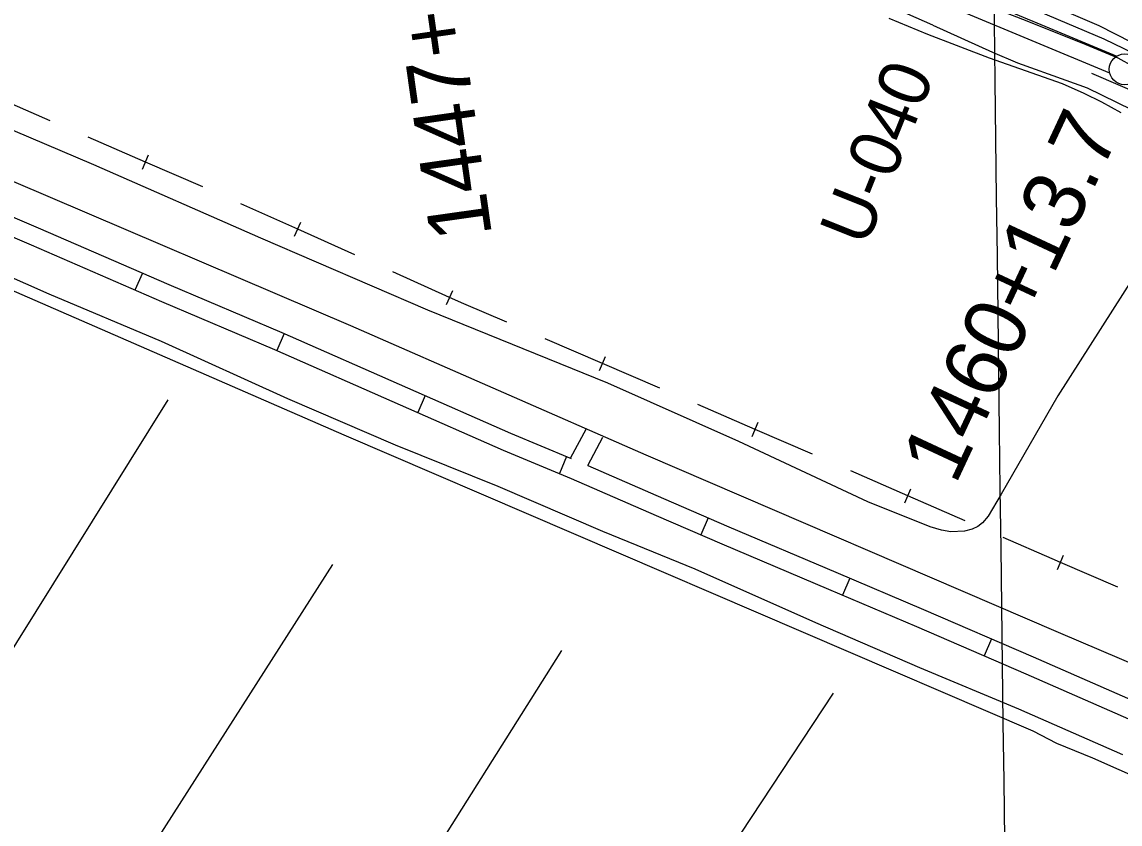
# Model space of a CAD drawing. Extents: x 3734862 to 3772949, y 391520 to 417239.
# Drawn here: x 3740026 to 3741807, y 404013 to 405314 of the extents above; entities that cross this region are included whole.
import ezdxf

# ---------------------------------------------------------------- set-up
doc = ezdxf.new("R2010")
doc.units = 0
for name, color, linetype in [('V-DTCH-CNTR', 7, 'Continuous'), ('V-FLOD-BASE', 7, 'Continuous'), ('V-GRID-MAJR', 7, 'Continuous'), ('V-LEVE-TOET', 7, 'Continuous'), ('V-RAIL-TRAK', 7, 'Continuous'), ('V-RIVR-EDGE', 7, 'Continuous'), ('V-RIVR-RANG-IDEN', 7, 'Continuous'), ('V-ROAD-CNTR', 7, 'Continuous'), ('V-RRAP-FSHR', 7, 'Continuous'), ('V-SITE-VEGE', 7, 'Continuous'), ('V-SURV-IDEN', 7, 'Continuous'), ('V-SURV-LINE', 7, 'Continuous'), ('V-TOPO-MINR', 7, 'Continuous'), ('V-TOPO-SHOR', 7, 'Continuous')]:
    doc.layers.add(name, color=color, linetype=linetype)

msp = doc.modelspace()

# ---------------------------------------------------------------- linework, layer by layer
at = {"layer": 'V-DTCH-CNTR'}
msp.add_lwpolyline([(3741974.8559930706, 404024.44664253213), (3741944.0631581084, 404044.97519917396), (3741899.5846187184, 404062.08232970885), (3741848.263227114, 404082.6108863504), (3741762.7275744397, 404120.2465735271), (3741704.5633306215, 404144.1965562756), (3741665.9262504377, 404164.015792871), (3740548.1213064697, 404644.43408793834), (3739663.390584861, 405029.7200473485), (3738935.6282170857, 405348.413371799)], dxfattribs=at)
at = {"layer": 'V-FLOD-BASE'}
msp.add_lwpolyline([(3741566.42, 405351.376), (3741658.144, 405314.952), (3741751.273, 405278.068), (3741803.036, 405256.38300000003), (3741828.798, 405242.037)], dxfattribs=at)
at = {"layer": 'V-GRID-MAJR'}
msp.add_spline([(3741709.628, 396887.316), (3741632.95, 402946.574), (3741556.258, 409006.89400000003), (3741479.5670000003, 415067.217), (3741479.554, 415068.275)], degree=3, dxfattribs=at)
at = {"layer": 'V-LEVE-TOET'}
for points in [[(3741503.139, 405309.107), (3741231.974, 405429.489), (3740957.71, 405546.288), (3740650.096, 405671.458), (3740361.478, 405794.487), (3740102.598, 405906.083), (3739811.915, 406027.064), (3739535.06, 406138.742)], [(3741628.659, 405352.199), (3741780.312, 405287.128), (3741845.3910000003, 405255.703), (3741955.395, 405188.083), (3742116.45, 405092.701), (3742264.876, 405000.525), (3742443.403, 404886.08400000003), (3742584.272, 404792.468), (3742604.416, 404780.428), (3742616.125, 404773.95), (3742646.525, 404765.232), (3742696.1010000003, 404751.478), (3742794.686, 404725.364), (3742931.427, 404690.103), (3743095.855, 404647.04600000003), (3743222.298, 404615.939), (3743373.072, 404576.548), (3743548.44, 404530.746), (3743737.366, 404483.145), (3743928.0700000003, 404434.619), (3744115.492, 404387.945)], [(3741503.139, 405309.107), (3741600.038, 405265.704), (3741640.292, 405248.163), (3741718.896, 405220.078), (3741753.522, 405207.645), (3741825.157, 405172.52)]]:
    msp.add_lwpolyline(points, dxfattribs=at)
at = {"layer": 'V-RAIL-TRAK'}
for points in [[(3740071.17, 405154.295), (3739978.271, 405194.56)], [(3740226.003, 405087.189), (3740133.1040000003, 405127.453)], [(3740221.032, 405075.719), (3740230.974, 405098.658)], [(3740318.903, 405046.924), (3740226.003, 405087.189)], [(3740473.021, 404978.197), (3740380.642, 405019.642)], [(3740467.904, 404966.792), (3740478.1380000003, 404989.601)], [(3740565.4, 404936.751), (3740473.021, 404978.197)], [(3740719.364, 404867.675), (3740626.986, 404909.121)], [(3740714.248, 404856.271), (3740724.481, 404879.08)], [(3740812.198, 404827.264), (3740742.468, 404857.31), (3740719.364, 404867.675)], [(3740967.173, 404760.487), (3740874.188, 404800.553)], [(3740962.227, 404749.007), (3740972.12, 404771.967)], [(3741060.159, 404720.42100000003), (3740967.173, 404760.487)], [(3741215.134, 404653.64400000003), (3741122.149, 404693.71)], [(3741210.188, 404642.164), (3741220.08, 404665.123)], [(3741308.119, 404613.577), (3741215.134, 404653.64400000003)], [(3741462.737, 404545.976), (3741369.967, 404586.538)], [(3741457.7290000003, 404534.523), (3741467.745, 404557.429)], [(3741555.507, 404505.414), (3741462.737, 404545.976)], [(3741710.149, 404437.87), (3741696.799, 404443.63800000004), (3741617.3540000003, 404478.373)], [(3741705.1920000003, 404426.395), (3741715.1070000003, 404449.344)], [(3741803.095, 404397.711), (3741710.149, 404437.87)]]:
    msp.add_lwpolyline(points, dxfattribs=at)
at = {"layer": 'V-RIVR-EDGE'}
msp.add_spline([(3740284.2251414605, 406091.4953103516), (3740310.8823887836, 406078.8939307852), (3740348.850922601, 406061.81651383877), (3740353.7003308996, 406060.5914132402), (3740364.615249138, 406059.3513143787), (3740372.6955965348, 406056.5007453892), (3740387.627191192, 406044.3327297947), (3740395.708538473, 406041.8865281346), (3740409.039661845, 406036.59675667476), (3740430.0417658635, 406026.43557946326), (3740442.5591551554, 406019.1259711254), (3740451.446237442, 406015.4646677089), (3740465.996462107, 406012.59810057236), (3740476.5040133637, 406010.1458996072), (3740489.4327691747, 406005.6658626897), (3740507.608301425, 405997.1291539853), (3740522.954262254, 405989.00381179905), (3740544.3577339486, 405977.62853271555), (3740556.473755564, 405971.5330262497), (3740569.8088784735, 405967.860724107), (3740577.487858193, 405966.22425698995), (3740592.041082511, 405964.57079184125), (3740596.8934904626, 405964.55879323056), (3740607.3960422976, 405960.0847556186), (3740616.67949284, 405953.1875136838), (3740635.667759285, 405946.26627452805), (3740666.7660480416, 405930.82332493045), (3740697.870336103, 405917.8065793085), (3740711.608826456, 405913.72890995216), (3740727.769521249, 405908.02777197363), (3740737.4643383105, 405903.96010145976), (3740772.597301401, 405884.8678470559), (3740794.413139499, 405876.72650672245), (3740819.459916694, 405866.9596979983), (3740836.4233468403, 405858.8303562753), (3740859.038920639, 405847.04771020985), (3740882.053862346, 405833.2422276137), (3740901.840864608, 405822.2753153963), (3740929.3028470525, 405808.0544667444), (3740946.262277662, 405798.3076557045), (3740968.879851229, 405787.3337442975), (3740998.357671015, 405770.6816922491), (3741025.4092868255, 405754.03563950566), (3741050.8534321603, 405741.4372595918), (3741073.4700058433, 405730.0589808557), (3741090.8378033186, 405721.9286392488), (3741112.2472743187, 405712.9795641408), (3741151.0305421, 405698.32635140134), (3741164.764033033, 405692.22684539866), (3741182.937565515, 405682.8814020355), (3741205.1587708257, 405675.143429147), (3741229.3978132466, 405665.78298752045), (3741250.811283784, 405658.45138172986), (3741277.4785299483, 405649.8936754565), (3741303.738409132, 405640.1238670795), (3741333.2262277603, 405627.51548832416), (3741357.457271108, 405614.920108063), (3741386.5417222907, 405602.71709652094), (3741400.2862119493, 405601.0656311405), (3741418.8691111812, 405593.74102453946), (3741447.554194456, 405583.56084952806), (3741468.5642975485, 405576.63461095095), (3741486.743829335, 405569.7153715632), (3741500.8786879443, 405562.4017636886), (3741512.5913421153, 405556.71162443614), (3741522.6905265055, 405552.64295403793), (3741537.2377515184, 405548.5632849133), (3741581.273795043, 405532.2796043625), (3741608.739777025, 405519.6762250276), (3741642.2532710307, 405499.7792355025), (3741662.8440085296, 405486.7884868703), (3741678.9967042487, 405477.8524102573), (3741697.168236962, 405467.69823223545), (3741715.3337703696, 405455.11785023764), (3741729.8729963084, 405447.8032424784), (3741754.1050395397, 405435.61222954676), (3741802.56612635, 405410.01710169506), (3741822.7624953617, 405401.0710262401), (3741865.5744381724, 405380.34230471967), (3741892.227685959, 405366.1234558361), (3741915.6569938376, 405356.3606466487), (3741930.6035867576, 405350.25814099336), (3741951.2093225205, 405343.33290230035), (3741972.626792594, 405337.6187658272), (3742009.0038540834, 405331.0588989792), (3742028.395487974, 405323.73229260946), (3742041.723611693, 405317.22941916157), (3742042.524347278, 405313.9924807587), (3742046.965388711, 405311.1509107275), (3742058.684042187, 405307.8869754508), (3742068.7932254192, 405307.86197834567), (3742073.6456333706, 405307.8499797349), (3742079.7181424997, 405310.66555277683), (3742088.618223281, 405312.2610246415), (3742095.0831011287, 405310.2231898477), (3742118.5114091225, 405300.05601333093), (3742134.2687364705, 405294.76024256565), (3742159.723880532, 405286.6099032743), (3742182.3504530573, 405279.2752978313), (3742201.342719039, 405273.9715279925), (3742222.3558217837, 405268.2583914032), (3742239.72861868, 405262.14988644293), (3742263.564293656, 405253.1948120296), (3742278.9102544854, 405245.0694698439), (3742307.9867065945, 405229.6315196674), (3742326.1582393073, 405219.4773416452), (3742346.3526085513, 405209.72253153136), (3742373.8245898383, 405199.54535617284), (3742400.8892041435, 405188.1560787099), (3742413.4055935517, 405180.4421030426), (3742429.9596569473, 405170.2919245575), (3742436.0041693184, 405161.78521237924), (3742439.2221099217, 405154.9029687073), (3742444.4658867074, 405149.6331949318), (3742450.526397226, 405147.5963600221), (3742468.3095607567, 405143.91305915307), (3742478.4117448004, 405141.05749074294), (3742497.4000112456, 405134.1362515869), (3742510.3247675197, 405128.03874535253), (3742527.692564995, 405119.90840374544), (3742545.0583627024, 405110.96932747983), (3742567.6769361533, 405100.3997834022), (3742590.6998769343, 405089.82923944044), (3742639.1599638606, 405063.8297442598), (3742649.265147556, 405062.1872778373), (3742658.9699634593, 405062.1632806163), (3742667.4626772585, 405062.54665037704), (3742676.7581264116, 405060.50181639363), (3742690.8999842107, 405056.018779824), (3742714.3282922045, 405045.85160330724), (3742740.9825398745, 405032.0371217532), (3742759.96380713, 405022.2853112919), (3742790.248361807, 405004.8225248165), (3742814.0870364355, 404997.0805523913), (3742826.612424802, 404993.0058826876), (3742844.39258868, 404988.1094798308), (3742862.983486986, 404984.0198118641), (3742878.743813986, 404979.9371430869), (3742899.75191731, 404972.2021698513), (3742910.66483578, 404970.15333633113), (3742935.3102452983, 404961.6006294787), (3742961.1707565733, 404953.8536576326), (3742978.5425535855, 404947.34078534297), (3742993.8905141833, 404940.0241778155), (3743010.454576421, 404933.91767262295), (3743026.218902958, 404931.4524731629), (3743054.51061763, 404925.72133865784), (3743082.401964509, 404921.60867335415), (3743104.22780145, 404917.5110063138), (3743119.989128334, 404913.8327048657), (3743140.19349642, 404908.1215680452), (3743171.309783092, 404899.9572303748), (3743202.021702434, 404891.7938925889), (3743227.882213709, 404884.0469207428), (3743293.3507255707, 404868.11461365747)], degree=3, dxfattribs=at)
at = {"layer": 'V-ROAD-CNTR'}
for p, q in [((3740220.9691469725, 404907.0787179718), (3740209.02189936, 404879.56030096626)), ((3740451.0455003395, 404809.1007467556), (3740438.967306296, 404781.6395517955)), ((3740679.890388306, 404708.3853130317), (3740667.76176438, 404680.9463538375)), ((3740915.6635104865, 404606.776152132), (3740941.5971665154, 404655.06505403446)), ((3740943.369426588, 404594.9584413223), (3740968.026833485, 404640.8709459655)), ((3740909.1144523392, 404609.49563695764), (3740897.609485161, 404581.78939704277)), ((3741138.750731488, 404510.1992537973), (3741126.8991051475, 404482.63951952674)), ((3741368.627999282, 404412.1002341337), (3741356.8975157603, 404384.4887192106)), ((3741598.524658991, 404313.6542346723), (3741586.6300633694, 404286.11301837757))]:
    msp.add_line(p, q, dxfattribs=at)
for points in [[(3738937.358086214, 405523.5119272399), (3740011.896937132, 405055.491863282), (3740558.814843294, 404822.18832989)], [(3738946.8946122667, 405425.5226950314), (3739037.1617365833, 405385.02819466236), (3739179.7516749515, 405321.9441741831), (3739323.71012415, 405259.51811085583), (3739448.36763632, 405206.85037448), (3739606.9563128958, 405138.96491234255), (3739823.898584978, 405045.1737683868), (3740040.347001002, 404952.79128574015), (3740252.1496659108, 404860.8361822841), (3740435.3077687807, 404783.24911774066), (3740639.0242904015, 404693.6489498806), (3740806.4458465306, 404619.64493693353), (3740916.578538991, 404573.91253095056), (3741054.245291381, 404513.8831390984), (3741160.660600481, 404468.1209242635), (3741334.045898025, 404394.1970067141), (3741476.4436779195, 404333.7006951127), (3741653.9468924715, 404257.0399937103), (3741829.2840582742, 404180.29102435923)], [(3739632.9313109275, 405160.41871870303), (3739835.739415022, 405072.7382316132), (3740052.2089989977, 404980.3467142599), (3740263.9743340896, 404888.4078177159), (3740447.1982312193, 404810.79288225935), (3740651.1277095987, 404721.0990501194), (3740818.26415347, 404647.2210630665), (3740916.471801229, 404606.440510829)], [(3740558.814843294, 404822.18832989), (3741037.3968861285, 404612.2527497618), (3741706.3545482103, 404324.430325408), (3741944.896071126, 404223.2195278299), (3742133.5146938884, 404151.26267174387), (3742385.8081893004, 404078.1188180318), (3742748.139464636, 404030.87491251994), (3743119.207722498, 404000.466973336), (3743219.937521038, 403989.8979944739), (3743882.616195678, 403933.75410676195), (3744432.7390954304, 403887.991198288), (3745126.1127086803, 403833.4703073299), (3745501.262958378, 403799.35037556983), (3746166.177628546, 403745.27548371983), (3747137.0766867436, 403655.899662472), (3747673.544613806, 403590.99179228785), (3747983.825993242, 403548.4198774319), (3748395.564169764, 403483.433007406), (3748723.02551484, 403408.7321568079), (3749121.862717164, 403263.6014470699), (3749450.4780599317, 403131.36171155), (3749678.7526033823, 403035.2229038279)], [(3740943.6398481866, 404594.84052436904), (3741066.1667086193, 404541.4128609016), (3741172.4693995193, 404495.6990757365), (3741345.794101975, 404421.8009932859), (3741488.2563220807, 404361.2773048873), (3741665.9091075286, 404284.5520062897), (3741841.049941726, 404207.88897564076), (3741912.2262842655, 404178.3483596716), (3741983.869882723, 404147.4145310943), (3742032.354389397, 404127.65730857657), (3742073.4176465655, 404111.56950101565), (3742102.2347012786, 404100.5836376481), (3742147.2250816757, 404084.6100769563), (3742242.4826900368, 404054.94676721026), (3742330.3535826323, 404033.57077978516), (3742382.5946208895, 404021.882857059)]]:
    msp.add_lwpolyline(points, dxfattribs=at)
at = {"layer": 'V-RRAP-FSHR'}
msp.add_lwpolyline([(3744483.722, 404317.65), (3744096.931, 404414.472), (3743639.216, 404531.05), (3743120.185, 404667.01900000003), (3742731.148, 404762.46), (3742601.7460000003, 404809.401), (3742448.9220000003, 404910.655), (3742129.46, 405108.342), (3741905.323, 405240.495), (3741772.841, 405307.906), (3741598.833, 405383.052), (3741291.509, 405502.327), (3740610.828, 405791.503), (3740295.501, 405923.923), (3740004.838, 406039.788)], dxfattribs=at)
at = {"layer": 'V-SITE-VEGE'}
for p, q in [((3741431.943, 405320.645), (3741494.362, 405294.603)), ((3741494.362, 405294.603), (3741594.415, 405256.238)), ((3741594.415, 405256.238), (3741672.724, 405228.811)), ((3741672.724, 405228.811), (3741712.904, 405214.694)), ((3740142.4560000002, 405082.62700000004), (3739814.336, 405222.542)), ((3741712.904, 405214.694), (3741748.18, 405198.914)), ((3741748.18, 405198.914), (3741776.49, 405185.146)), ((3741776.49, 405185.146), (3741808.091, 405167.70900000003)), ((3740413.1750000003, 404963.695), (3740142.4560000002, 405082.62699999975)), ((3740683.882, 404847.222), (3740413.1750000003, 404963.695)), ((3741863.2060000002, 404954.77), (3741706.092, 404708.00300000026)), ((3740975.88, 404728.39900000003), (3740683.882, 404847.222)), ((3741188.358, 404633.726), (3740975.88, 404728.39900000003)), ((3741706.092, 404708.00300000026), (3741614.012, 404548.33)), ((3741397.989, 404536.17100000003), (3741188.358, 404633.726)), ((3741498.873, 404495.355), (3741397.989, 404536.17100000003)), ((3741614.012, 404548.33), (3741592.911, 404513.025)), ((3741583.554, 404501.929), (3741576.218, 404496.16200000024)), ((3741592.911, 404513.025), (3741583.554, 404501.929)), ((3741517.318, 404490.128), (3741498.873, 404495.355)), ((3741532.475, 404487.343), (3741517.318, 404490.128)), ((3741554.569, 404488.277), (3741532.475, 404487.343)), ((3741566.828, 404491.61100000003), (3741554.569, 404488.277)), ((3741576.218, 404496.16200000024), (3741566.828, 404491.61100000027))]:
    msp.add_line(p, q, dxfattribs=at)
at = {"layer": 'V-SURV-LINE'}
for points in [[(3740694.0995441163, 405720.71528205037), (3741801.720506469, 405259.1420303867)], [(3741790.184075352, 405231.4488765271), (3740682.563652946, 405693.02190318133)]]:
    msp.add_lwpolyline(points, dxfattribs=at)
msp.add_circle((3741814.40153, 405237.60672000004), 25, dxfattribs=at)
at = {"layer": 'V-TOPO-MINR'}
msp.add_lwpolyline([(3741760.42, 405231.63), (3742147.5188653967, 405064.58992227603), (3742224.3556219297, 405030.6361044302), (3742300.77986431, 404995.7978619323), (3742376.5853354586, 404959.63298245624), (3742451.9782924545, 404922.583678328), (3742579.804748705, 404858.378627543), (3742591.076164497, 404853.01067024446), (3742602.482084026, 404847.96487141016), (3742614.089759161, 404843.4023102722), (3742625.8319380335, 404839.1619075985), (3743100.43, 404678.96)], dxfattribs=at)
at = {"layer": 'V-TOPO-SHOR'}
for p, q in [((3739392.5512778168, 403308.70634054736), (3740262.9452182, 404701.33664515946)), ((3739729.1036014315, 403181.0485626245), (3740529.8660265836, 404434.41583677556)), ((3740088.866430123, 403006.9697745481), (3740901.2341078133, 404295.15280631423)), ((3740437.0240062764, 402856.1014915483), (3741342.2337042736, 404225.5212910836))]:
    msp.add_line(p, q, dxfattribs=at)
msp.add_lwpolyline([(3739056.992, 405310.068), (3739177.127, 405255.832), (3739376.25, 405169.501), (3739570.882, 405088.021), (3739846.4590000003, 404972.017), (3740069.455, 404873.213), (3740251.463, 404796.788), (3740456.31, 404703.659), (3740630.919, 404628.333), (3740797.355, 404561.743), (3740967.565, 404488.67), (3741116.909, 404427.273), (3741312.866, 404340.52), (3741481.531, 404267.439), (3741641.957, 404200.412), (3741810.872, 404126.113)], dxfattribs=at)

# ---------------------------------------------------------------- texts
at = {"layer": 'V-RIVR-RANG-IDEN'}
msp.add_text('U-040', height=83, rotation=68.25032571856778, dxfattribs=at).set_placement((3741394.6890574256, 404947.5890844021))
at = {"layer": 'V-SURV-IDEN'}
for s, height, rotation, p in [('1447+73.7', 99.99999999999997, 98.03888310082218, (3740788.387120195, 404968.13344623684)), ('1460+13.7', 100.00000000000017, 64.99183371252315, (3741539.765353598, 404562.02593485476))]:
    msp.add_text(s, height=height, rotation=rotation, dxfattribs=at).set_placement(p)

doc.saveas('drawing.dxf')
